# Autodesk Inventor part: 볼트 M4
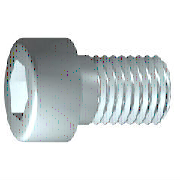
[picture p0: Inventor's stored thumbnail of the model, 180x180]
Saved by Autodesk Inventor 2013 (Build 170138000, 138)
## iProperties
IsCustomPart: 0
Created: 2012-02
Part Number: 볼트 M4
Material: 스테인리스강
Description: 6각 소켓 머리 캡 나사
Document SubType Name: Modeling
Standard: ISO 4762
Designer: mduedu
Standard Revision: Fourth edition 2004-03-01
Standards Organization: ISO
Language: ko-KR
Size Designation: M4 x 12
Categories: <MemberInstance><Categories><Category DisplayName="조임쇠" InternalName="e4da775c-781d-43d5-af7c-5136215cf5a6" Mnemonic="FSTN"><Category DisplayName="볼트" InternalN
Density: 8.08 g/cm^3
Author: mduedu
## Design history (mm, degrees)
sketch "스케치1"
  geometry: L1 (-1, 0)-(12, 0); L2 (12, 0)-(12, 2); L3 (12, 2)-(1.75, 2); L4 (1.75, 2)-(1.32, 2); L5 (1.32, 2)-(0, 2); L6 (0, 2)-(0, 3.5); L7 (0, 3.5)-(-4, 3.5); L8 (-4, 3.5)-(-4, 1.732); L9 (-4, 1.732)-(-2, 1.732); L10 (-2, 1.732)-(-1, 0); L11 (-7.2, 0)-(15.2, 0) reference; L12 (0, -0.7)-(0, 4.2) reference; L13 (1.75, 2)-(0, 2)
  constraints: 22 end point, 6 parallel, 2 collinear, 2 perpendicular, 1 horizontal, 1 point on line
  dimensions: "d1" = 10.25 distance from line of L3.end L2 (= GEL); "d2" = 0.42952 distance of L4.end L3.end (computed from GAL); "d3" = 4 distance between parallel lines of L8 L6 (= KOH); "d4" = 2 distance of L8.end L9.end (= INTI); "d5" = 60 deg angle of L10 L1; "d6" = 4 diameter of L3 L1 (= GD); "d7" = 4 diameter of L5 L1 (= BDM); "d8" = 3.4641 diameter of L9 L1 (= 1.1547 x SW); "d9" = 7 diameter of L7 L1 (= KOD); "d26" = 12 distance between parallel lines of L12 L2 (= NLG)
revolve "본체" sketch "스케치1" stored, may be unused: angle "d10" = 90 deg
sketch "스케치2"
  geometry: L1 (0, -4.9)-(0, 4.9) reference; L2 (-4.9, 0)-(4.9, 0) reference; L3 (1.732, 0)-(0.866, -1.5); L4 (0.866, -1.5)-(-0.866, -1.5); L5 (-0.866, -1.5)-(-1.732, 0); L6 (-1.732, 0)-(-0.866, 1.5); L7 (-0.866, 1.5)-(0.866, 1.5); L8 (0.866, 1.5)-(1.732, 0); 2 further points
  constraints: 12 end point, 1 coincident, 1 horizontal alignment, 1 point on line, 12 other
extrude "슬롯" join sketch "스케치2" stored distance "d11" = 10; taper "d12" = 0 deg
workplane "Work Plane1"
fillet "Fillet2" dims "d30" = 0.1 (= R)
body "Solid1"
fillet "모깎기1" dims "d17" = 0.4 (= RR)
feature "스레드" dims "d13" = 10.25 (= GEL), "d14" = 0
chamfer "모따기1" distance "d15" = 0.42941 (= -0.5 x SPD + 0.5 x GD); stored, may be unused: second distance "d16" = 0.42941 (= GUL), angle "d27" = 45 deg
other parameters: "GD" = 4 [user parameter; used in 2 equation terms], "NLG" = 12 [user parameter; used in 1 equation term], "GEL" = 10.25 [user parameter; used in 2 equation terms], "KOD" = 7 [user parameter; used in 1 equation term], "KOH" = 4 [user parameter; used in 1 equation term], "INTI" = 2 [user parameter; used in 1 equation term], "GAL" = 0.42941 (= 0.61345 x PTC) [user parameter; used in 1 equation term], "GUL" = 0.42941 (= 0.61345 x PTC) [user parameter; used in 1 equation term], "BDM" = 4 (= NND) [user parameter; used in 1 equation term], "SW" = 3 [user parameter; used in 2 equation terms], "RR" = 0.4 [user parameter; used in 1 equation term], "SPD" = 3.14117 (= NND - 1.2269 x PTC) [user parameter; used in 1 equation term], "d19" = 0, "d28" = 0, "d29" = 0, "R" = 0.1 [user parameter; used in 1 equation term], "TOA" = 30 deg [user parameter], "GD1" = 3.14117 (= THREADDIA - 1.2269 x PTC) [user parameter], "THREADDIA" = 4 [user parameter; used in 1 equation term], "FAWI" = 45 deg [user parameter], "TPU" = 14.28571 (computed from PTC) [user parameter], "PTC" = 0.7 [user parameter; used in 5 equation terms], "NND" = 4 [user parameter; used in 2 equation terms], "E0" = 3.465 (= 1.155 x SW) [user parameter]
